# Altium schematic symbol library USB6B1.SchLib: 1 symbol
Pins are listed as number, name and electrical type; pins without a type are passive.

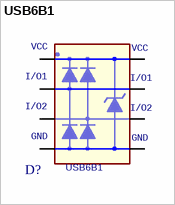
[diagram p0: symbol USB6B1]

## USB6B1
designator D?
footprint ST_SO8
pins: 1 VCC, 2 I/O1, 3 I/O2, 4 GND, 5 GND1, 6 I/O2+, 7 I/O1+, 8 VCC1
